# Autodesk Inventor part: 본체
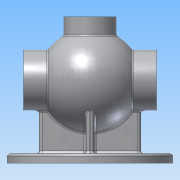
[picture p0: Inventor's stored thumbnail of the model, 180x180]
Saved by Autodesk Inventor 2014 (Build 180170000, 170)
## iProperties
Created: 2020-08
Part Number: 본체
Material: 알루미늄 6061
Document SubType Name: Modeling
Designer: kb542
Mass: 1759.18 g
Surface Area: 1342.58 cm^2
Volume: 649.145 cm^3
Density: 2.71 g/cm^3
Appearance: 알루미늄 - 평지
Author: kb542
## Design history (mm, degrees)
sketch "스케치1"
  geometry: L1 (-68, 0)-(68, 0); L2 (-68, 0)-(-68, 31); L3 (-68, 31)-(-42.988, 31); L4 (42.988, 31)-(68, 31); L5 (68, 31)-(68, 0); L6 (-52, 17.5)-(-52, 18.5); L7 (-52, 18.5)-(-50.25, 18.5); L8 (-50.25, 18.5)-(-50.25, 17.5); L9 (-50.25, 17.5)-(-39.278, 17.5); L10 (39.278, 17.5)-(68, 17.5); L11 (-52, 17.5)-(-68, 17.5); A1 r 43 centre (0, 0) between (39.278, 17.5) and (-39.278, 17.5); A2 r 53 centre (0, 0) between (42.988, 31) and (-42.988, 31); 2 further points
  constraints: 22 end point, 4 horizontal, 4 perpendicular, 4 point on circle, 3 coincident, 2 centre point, 2 point on line, 1 midpoint, 1 parallel, 1 vertical
  dimensions: "d0" = 136 distance of L1.start L1.end; "d1" = 62 diameter of L3 L1; "d2" = 62 diameter of L4 L1; "d8" = 35 diameter of L11 L1; "d9" = 37 diameter of L7 L1; "d10" = 1.75 distance of L6.end L7.end; "d11" = 35 diameter of L9 L1; "d12" = 43 radius of A1; "d13" = 35 diameter of L10 L1; "d14" = 16 distance of L6.start L11.end; "d16" = 53 radius of A2
revolve "회전1" sketch "스케치1" stored, may be unused: angle "d15" = 90 deg
chamfer "모따기1" distance "d17" = 1; stored, may be unused: second distance "d18" = 2, angle "d19" = 45 deg
sketch "스케치2"
  geometry: L1 (-27, 45.607)-(27, 45.607); L2 (-27, 45.607)-(27, 45.607); A1 r 53 centre (0, 0) between (-27, 45.607) and (27, 45.607) reference; A2 r 53 centre (0, 0) between (27, 45.607) and (-27, 45.607); 1 further point
  constraints: 4 end point, 4 point on circle, 2 horizontal, 1 centre point, 1 concentric
  dimensions: "d20" = 54 distance of L1.start L1.end; "d21" = 45.60702 distance from line of A2.centre L1
extrude "돌출1" cut sketch "스케치2" stored distance "d22" = 10; taper "d23" = 0 deg
sketch "스케치3"
  geometry: 2 further points
  constraints: 1 horizontal alignment
  dimensions: "d24" = 24 distance of point (0, 0) point (-24, 0)
hole "구멍1" sketch "스케치3" at (-24, 0) diameter "d25" = 3.242; stored, may be unused: countersink angle "d29" = 90 deg, drill point angle "d31" = 118 deg; dims "d26" = 12, "d27" = 4, "d28" = 2, "d30" = 15
sketch "스케치4"
  geometry: 2 further points
  constraints: 1 horizontal alignment
  dimensions: "d35" = 24 distance of point (0, 0) point (24, 0)
hole "구멍2" sketch "스케치4" at (24, 0) diameter "d36" = 3.242; stored, may be unused: countersink angle "d40" = 90 deg, drill point angle "d42" = 118 deg; dims "d37" = 12, "d38" = 4, "d39" = 2, "d41" = 15
node "작업 평면1"
sketch "스케치6"
  geometry: C1 r 85 at (0, 0); 1 further point
  constraints: 1 centre point, 1 coincident
  dimensions: "d47" = 170 diameter of C1
extrude "돌출2" join sketch "스케치6" distance "d48" = 10; taper "d49" = 0 deg
fillet "모깎기1" dims "d50" = 3
sketch "스케치7"
  geometry: A1 r 72.5 centre (0, 0) between (0, -72.5) and (72.5, 0); 3 further points
  constraints: 4 point on circle, 2 horizontal alignment, 2 vertical alignment, 1 centre point, 1 coincident
  dimensions: "d51" = 145 diameter of A1
hole "구멍3" sketch "스케치7" at (0, -72.5), (72.5, 0), (0, 72.5), (-72.5, 0) diameter "d52" = 9; stored, may be unused: countersink angle "d56" = 90 deg, drill point angle "d58" = 118 deg; dims "d53" = 12, "d54" = 4, "d55" = 2, "d57" = 15
sketch "스케치8"
  geometry: L1 (-82, -75)-(82, -75) reference; L2 (43, 0)-(43, -75); L3 (-43, 0)-(-43, -75); L4 (43, -75)-(-43, -75); A1 r 43 centre (0, 0) between (43, 0) and (-43, 0) reference; A2 r 43 centre (0, 0) between (-43, 0) and (43, 0); 1 further point
  constraints: 6 end point, 4 point on circle, 2 point on line, 1 centre point, 1 collinear, 1 concentric, 1 parallel, 1 perpendicular
  dimensions: "d59" = 43 distance from line of point (0, 0) L2; "d60" = 86 distance between parallel lines of L3 L2
extrude "돌출3" join sketch "스케치8" stored distance "d61" = 8; taper "d62" = 0 deg
sketch "스케치10"
  geometry: L1 (-68, -31)-(-42.988, -31) reference; L2 (42.988, -31)-(68, -31) reference; L3 (-82, -75)-(82, -75) reference; L4 (-52, -31)-(-52, -75); L5 (52, -31)-(52, -75); 1 further point
  constraints: 4 end point, 4 point on line, 2 perpendicular
  dimensions: "d63" = 52 distance from line of point (0, 0) L4; "d64" = 104 distance between parallel lines of L5 L4
feature "리브1" dims "d65" = 1, "d66" = 8, "d67" = 0, "d68" = 0, "d69" = 1, "d70" = 1
feature "리브2" dims "d71" = 1, "d72" = 8, "d73" = 0, "d74" = 0, "d75" = 1, "d76" = 1
fillet "모깎기2" dims "d77" = 3
fillet "모깎기3" dims "d78" = 3
fillet "모깎기4" dims "d79" = 3
fillet "모깎기5" dims "d80" = 3
node "작업 평면2"
sketch "스케치11"
  geometry: C1 r 27 at (0, 0); 1 further point
  constraints: 1 centre point, 1 coincident
  dimensions: "d82" = 54 diameter of C1
extrude "돌출4" join sketch "스케치11" stored distance "d83" = 8; taper "d84" = 0 deg
sketch "스케치12"
  geometry: C1 r 13 at (0, 0); 1 further point
  constraints: 1 centre point, 1 coincident
  dimensions: "d85" = 26 diameter of C1
extrude "돌출5" cut sketch "스케치12" stored distance "d86" = 8; taper "d87" = 0 deg
chamfer "모따기2" distance "d88" = 1; stored, may be unused: second distance "d89" = 2, angle "d90" = 45 deg
fillet "모깎기6" dims "d91" = 3
sketch "스케치13"
  geometry: 2 further points
  constraints: 1 vertical alignment
  dimensions: "d92" = 20 distance of point (0, 0) point (0, 20)
hole "구멍4" sketch "스케치13" at (0, 20) diameter "d93" = 3.242; stored, may be unused: countersink angle "d97" = 90 deg, drill point angle "d99" = 118 deg; dims "d94" = 12, "d95" = 4, "d96" = 2, "d98" = 15
node "작업 평면3"
node "작업 평면4"
sketch "스케치17"
  geometry: L1 (-27, 65)-(27, 65) reference; L2 (-27, 65)-(-27, 47.286) reference; 2 further points
  constraints: 1 other
  dimensions: "d109" = 9 distance from line of point (0, 56) L1; "d110" = 27 distance from line of point (0, 56) L2
feature "엠보싱2" sketch "스케치17" dims "d0" = 136, "d1" = 62, "d2" = 62, "d8" = 35, "d9" = 37, "d10" = 1.75, "d11" = 35, "d12" = 43, "d13" = 35, "d14" = 16, "d16" = 53, "d111" = 0.5, "d112" = 0
node "솔리드1"
pattern_circular "원형 패턴1" dims angle "d33" = 360 deg
pattern_circular "원형 패턴2" dims angle "d44" = 360 deg
pattern_circular "원형 패턴3" dims angle "d101" = 360 deg
other parameters: "d46" = -85
